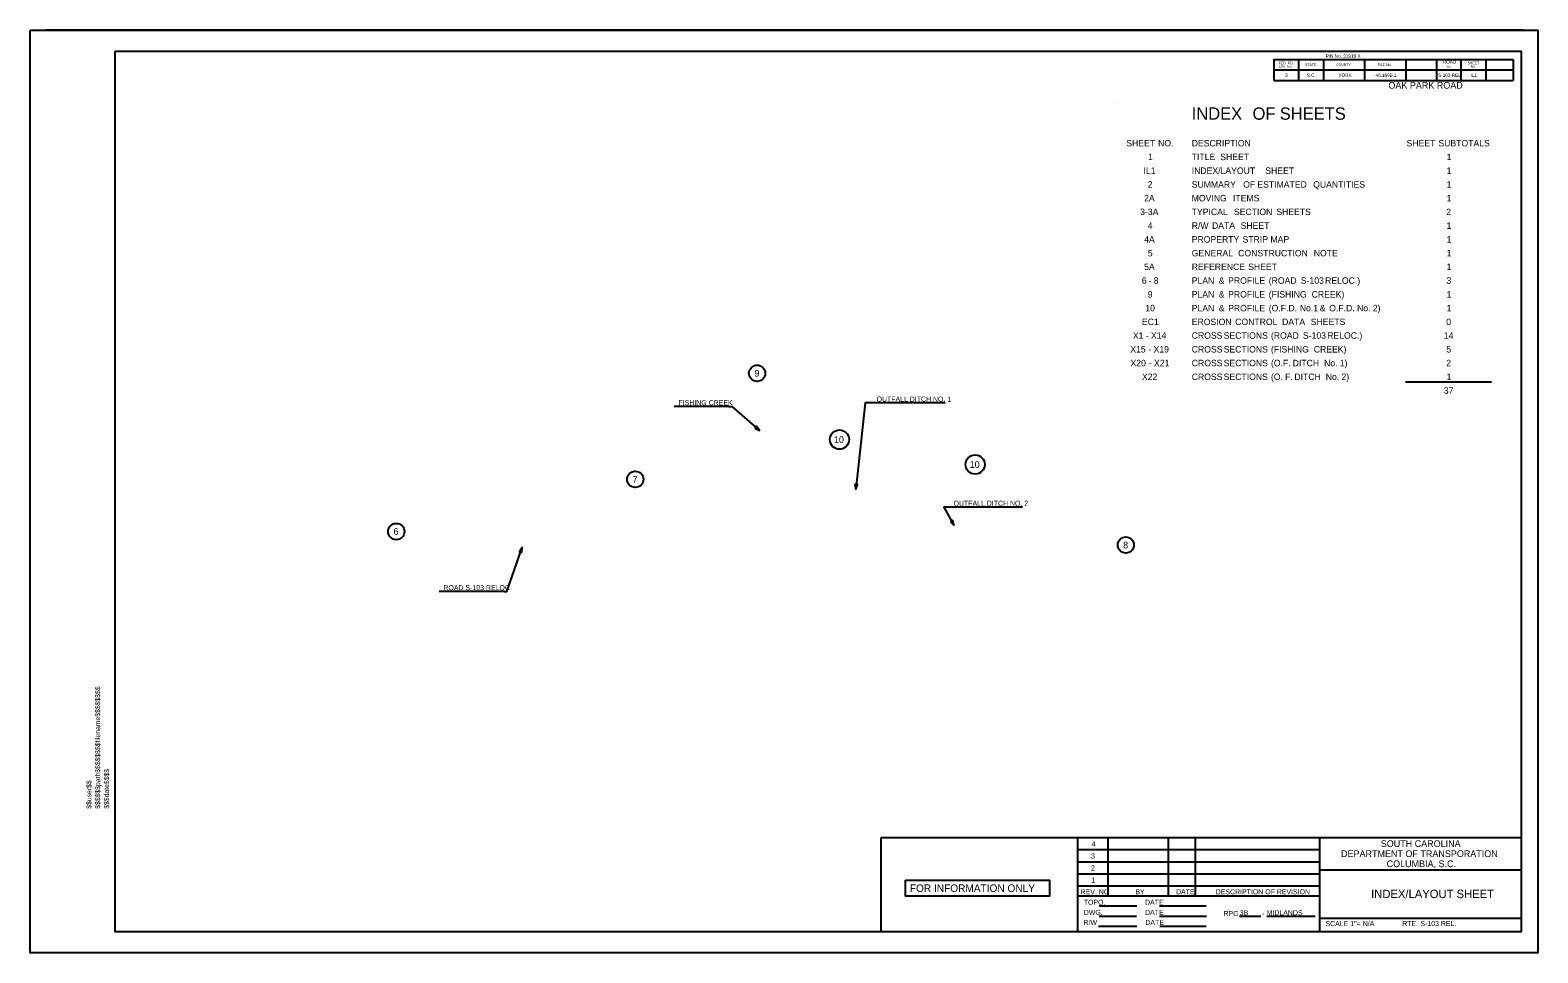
# Model space of a CAD drawing. Extents: x -796 to 2793, y -4650 to 4425.
# Drawn here: x 981 to 2777, y -125 to 975 of the extents above; entities that cross this region are included whole.
import ezdxf

# ---------------------------------------------------------------- set-up
doc = ezdxf.new("R2010")
doc.units = 0
for name, color, linetype in [('RD_HC_CL', 7, 'Continuous'), ('RD_HC_Data', 7, 'Continuous'), ('RD_HC_Data_Tic', 7, 'Continuous'), ('RD_SHT_Bndy', 7, 'Continuous'), ('RD_TX_Misc1', 7, 'Continuous')]:
    doc.layers.add(name, color=color, linetype=linetype)

msp = doc.modelspace()

# ---------------------------------------------------------------- linework, layer by layer
at = {"layer": 'RD_HC_CL'}
msp.add_lwpolyline([(981.4, 975), (2777.4, 975), (2777.4, -125), (981.4, -125)], close=True, dxfattribs=at)
at = {"layer": 'RD_HC_Data'}
for p, q in [((2760, 975), (1000, 975)), ((1000, 975), (2760, 975)), ((2463.1, 940), (2463.1, 915)), ((2463.1, 940), (2748.1, 940)), ((2492.1, 940), (2492.1, 915)), ((2522.1, 940), (2522.1, 915)), ((2571.1, 940), (2571.1, 915)), ((2620.1, 940), (2620.1, 915)), ((2656.6, 940), (2656.6, 915)), ((2685.6, 940), (2685.6, 915)), ((2715.6, 940), (2715.6, 915)), ((2748.1, 940), (2748.1, 915)), ((2463.1, 927.5), (2748.1, 927.5)), ((2463.1, 915), (2748.1, 915)), ((1995, 12.5), (2757.6, 12.5)), ((1995, -100), (1995, 12.5)), ((2229.6, -100), (2229.6, 12.5)), ((2229.6, 12.5), (2229.6, 12.5)), ((2265.6, -57.2), (2265.6, 12.5)), ((2337.6, -57.2), (2337.6, 12.5)), ((2369.4, -57.1), (2369.4, 12.5)), ((2517.6, -100), (2517.6, 12.5)), ((2229.6, -1.9), (2517.6, -1.9)), ((2229.6, -16.3), (2517.6, -16.3)), ((2229.6, -30.7), (2517.6, -30.7)), ((2517.6, -25.9), (2757.6, -25.9)), ((2229.6, -45.1), (2517.6, -45.1)), ((2229.6, -57.1), (2517.6, -57.1)), ((2255, -69.1), (2299.9, -69.1)), ((2326.8, -69.1), (2382.1, -69.1)), ((2255, -81.1), (2299.5, -81.1)), ((2326.8, -81.1), (2382.5, -81.1)), ((2422.1, -81.1), (2447.3, -81.1)), ((2454.5, -81.1), (2512, -81.1)), ((2517.6, -83.5), (2757.6, -83.5)), ((2254.2, -93.1), (2299.9, -93.1)), ((2327.2, -93.1), (2382.1, -93.1)), ((2760, -125), (1000, -125)), ((2760, -125), (1000, -125))]:
    msp.add_line(p, q, dxfattribs=at)
msp.add_lwpolyline([(1082.6, 950), (2757.6, 950), (2757.6, -100), (1082.6, -100)], close=True, dxfattribs=at)
at = {"layer": 'RD_HC_Data_Tic'}
msp.add_lwpolyline([(2024.3, -38.4), (2195.8, -38.4), (2195.8, -57.4), (2024.3, -57.4)], close=True, dxfattribs=at)
for centre, radius in [((1847.4, 565.9), 9.73), ((1945.5, 486.9), 11.5), ((2107.1, 457.2), 11.5), ((1702.2, 439.5), 9.72), ((1417.5, 377.3), 9.73), ((2286.6, 361.2), 9.67)]:
    msp.add_circle(centre, radius, dxfattribs=at)
at = {"layer": 'RD_SHT_Bndy'}
for p, q in [((2277.7, 887.3), (2277.7, 887.3)), ((2619.7, 555.6), (2722, 555.6)), ((1813.6, 526.4), (1748.7, 526.4)), ((2071.4, 530.7), (1984.7, 530.7)), ((2163.7, 406.5), (2076.4, 406.5)), ((1546.1, 305.9), (1468.7, 305.9))]:
    msp.add_line(p, q, dxfattribs=at)
for points in [[(1813.6, 526.4), (1817.1, 526.4), (1850.2, 497.8)], [(1984.7, 530.7), (1975.9, 530.7), (1964.9, 427.8)], [(2076.4, 406.5), (2069.8, 406.5), (2081.9, 384.7)], [(1546.1, 305.9), (1549.3, 305.9), (1567.6, 358.1)]]:
    msp.add_lwpolyline(points, dxfattribs=at)
for points in [[(1844.8, 500.4), (1850.2, 497.8), (1846.8, 502.7)], [(1963.9, 433.8), (1964.9, 427.8), (1967, 433.4)], [(2077.7, 389), (2081.9, 384.7), (2080.4, 390.5)], [(1567.2, 352.1), (1567.6, 358.1), (1564.2, 353.1)]]:
    msp.add_lwpolyline(points, close=True, dxfattribs=at)

# ---------------------------------------------------------------- texts
at = {"layer": 'RD_HC_Data_Tic'}
for s, height, p in [('FED. RD.', 3, (2468.7, 934.3)), ('STATE', 3, (2500.1, 932.3)), ('PIN No. 31919 X   ', 4, (2524.7, 942)), ('COUNTY', 3, (2537.1, 932.3)), ('FILE No.', 3, (2586.6, 932.3)), ('      ROAD      ', 4, (2655, 935.1)), ('SHEET', 3, (2693.7, 934.3)), ('DIV. No.', 3, (2469.3, 930.2)), ('3', 4, (2476.4, 919.3)), ('S.C.', 4, (2502.1, 919.3)), ('      YORK      ', 4, (2530.7, 919.3)), ('   46.169B.1    ', 4, (2579.4, 919.3)), ('   S-103 REL.   ', 4, (2653.9, 919.3)), ('No.', 3, (2667.9, 930.2)), ('      IL1       ', 4, (2688, 919.3)), ('No.', 3, (2697.4, 930.2)), ('OAK PARK ROAD                 ', 8, (2599.4, 905.2)), ('4', 6.24, (2245.8, 1.9)), ('SOUTH CAROLINA', 8, (2590.3, 1.2)), ('3', 6.24, (2245, -12.5)), ('DEPARTMENT OF TRANSPORATION', 8, (2543, -10.8)), ('COLUMBIA, S.C.', 8, (2597.3, -22.8)), ('2', 6.24, (2245, -26.9)), ('1', 6.24, (2245.4, -41.3)), ('FOR INFORMATION ONLY', 9, (2029.3, -52.4)), ('REV. NO.', 6, (2232.7, -55.2)), ('BY', 6, (2297.9, -55.2)), ('DATE', 6, (2346.4, -55.2)), ('DESCRIPTION OF REVISION', 6, (2393.7, -55.2)), ('      INDEX/LAYOUT SHEET       ', 10, (2556.5, -59.7)), ('TOPO.', 6, (2236.5, -67.7)), ('DATE', 6, (2309.5, -67.7)), ('R/W', 6, (2236.2, -91.7)), ('DWG.', 6, (2236.5, -79.7)), ('DATE', 6, (2309.5, -79.7)), ('DATE', 6, (2309.9, -91.7)), ('RPG', 6, (2403, -81.1)), ('3B    ', 6, (2422.3, -80.1)), ('-', 6, (2448.7, -81.1)), ('MIDLANDS   ', 6, (2454.3, -80.1)), ('SCALE 1"=', 6, (2524.4, -93.1)), ('N/A        ', 6, (2568.8, -93)), ('RTE.', 6, (2615.8, -93.1)), ('S-103 REL. ', 6, (2637.5, -93))]:
    msp.add_text(s, height=height, dxfattribs=at).set_placement(p)
at = {"layer": 'RD_SHT_Bndy'}
for s, height, p in [('INDEX', 14.7, (2365.1, 868.2)), (' OF', 14.7, (2432.1, 868.2)), (' SHEETS', 14.7, (2464.5, 868.2)), ('SHEET', 7.7, (2287.1, 836.4)), (' NO.', 7.7, (2322.2, 836.4)), ('DESCRIPTION', 7.7, (2365.1, 836.4)), ('SHEET', 7.7, (2621, 836.4)), (' SUBTOTALS', 7.7, (2656.1, 836.4)), ('1', 7.7, (2313.1, 820)), ('TITLE', 7.7, (2365.1, 820)), (' SHEET', 7.7, (2396.2, 820)), ('1', 7.7, (2668.7, 820)), ('IL1', 7.7, (2307.7, 803.6)), ('INDEX/LAYOUT', 7.7, (2365.1, 803.6)), (' SHEET', 7.7, (2449.8, 803.6)), ('1', 7.7, (2668.7, 803.6)), ('2', 7.7, (2312.7, 787.2)), ('SUMMARY', 7.7, (2365.1, 787.2)), (' OF', 7.7, (2423.5, 787.2)), (' ESTIMATED', 7.7, (2440.4, 787.2)), (' QUANTITIES', 7.7, (2506.9, 787.2)), ('1', 7.7, (2668.7, 787.2)), ('2A', 7.7, (2308.4, 770.9)), ('MOVING', 7.7, (2365.1, 770.9)), (' ITEMS', 7.7, (2411.4, 770.9)), ('1', 7.7, (2668.7, 770.9)), ('3-3A', 7.7, (2303.7, 754.5)), ('TYPICAL', 7.7, (2365.1, 754.5)), (' SECTION', 7.7, (2412.5, 754.5)), (' SHEETS', 7.7, (2463, 754.5)), ('2', 7.7, (2668.3, 754.5)), ('4', 7.7, (2312.7, 738.1)), ('R/W', 7.7, (2365.1, 738.1)), (' DATA', 7.7, (2386.4, 738.1)), (' SHEET', 7.7, (2420.5, 738.1)), ('1', 7.7, (2668.7, 738.1)), ('4A', 7.7, (2308.4, 721.7)), ('PROPERTY', 7.7, (2365.1, 721.7)), (' STRIP', 7.7, (2422.8, 721.7)), (' MAP', 7.7, (2456, 721.7)), ('1', 7.7, (2668.7, 721.7)), ('5', 7.7, (2312.8, 705.3)), ('GENERAL', 7.7, (2365.1, 705.3)), (' CONSTRUCTION', 7.7, (2417.6, 705.3)), (' NOTE', 7.7, (2507.6, 705.3)), ('1', 7.7, (2668.7, 705.3)), ('5A', 7.7, (2308.4, 689)), ('REFERENCE', 7.7, (2365.1, 689)), (' SHEET', 7.7, (2429.5, 689)), ('1', 7.7, (2668.7, 689)), ('6', 7.7, (2305.7, 672.6)), (' -', 7.7, (2310.9, 672.6)), (' 8', 7.7, (2317, 672.6)), ('PLAN', 7.7, (2365.1, 672.6)), (' &', 7.7, (2394.5, 672.6)), (' PROFILE', 7.7, (2405.6, 672.6)), (' (ROAD', 7.7, (2454, 672.6)), (' S-103', 7.7, (2492.2, 672.6)), (' RELOC.)', 7.7, (2521.1, 672.6)), ('3', 7.7, (2668.5, 672.6)), ('10', 7.7, (2309.8, 639.8)), ('9', 7.7, (2312.7, 656.2)), ('PLAN', 7.7, (2365.1, 656.2)), ('PLAN', 7.7, (2365.1, 639.8)), (' &', 7.7, (2394.5, 656.2)), (' &', 7.7, (2394.5, 639.8)), (' PROFILE', 7.7, (2405.6, 656.2)), (' PROFILE', 7.7, (2405.6, 639.8)), (' (FISHING', 7.7, (2454, 656.2)), (' (O.F.D.', 7.7, (2454, 639.8)), (' No.1', 7.7, (2491, 639.8)), (' CREEK)', 7.7, (2505.1, 656.2)), (' &', 7.7, (2514.8, 639.8)), (' O.F.D.', 7.7, (2526, 639.8)), (' No.', 7.7, (2559.2, 639.8)), (' 2)', 7.7, (2577.9, 639.8)), ('1', 7.7, (2668.7, 656.2)), ('1', 7.7, (2668.7, 639.8)), ('EC1', 7.7, (2305.8, 623.4)), ('EROSION', 7.7, (2365.1, 623.4)), (' CONTROL', 7.7, (2414, 623.4)), (' DATA', 7.7, (2469.9, 623.4)), (' SHEETS', 7.7, (2504, 623.4)), ('0', 7.7, (2668.3, 623.4)), ('X1', 7.7, (2295, 607.1)), (' X14', 7.7, (2313.7, 607.1)), ('CROSS', 7.7, (2365.1, 607.1)), (' SECTIONS', 7.7, (2400.3, 607.1)), (' (ROAD', 7.7, (2456.6, 607.1)), (' S-103', 7.7, (2494.7, 607.1)), (' RELOC.)', 7.7, (2523.6, 607.1)), ('14', 7.7, (2665.4, 607.1)), ('X15', 7.7, (2291.9, 590.7)), (' -', 7.7, (2307.6, 607.1)), (' -', 7.7, (2310.6, 590.7)), (' X19', 7.7, (2316.8, 590.7)), ('CROSS', 7.7, (2365.1, 590.7)), (' SECTIONS', 7.7, (2400.3, 590.7)), (' (FISHING', 7.7, (2456.6, 590.7)), (' CREEK)', 7.7, (2507.6, 590.7)), ('5', 7.7, (2668.4, 590.7)), ('X20', 7.7, (2292.2, 574.3)), (' -', 7.7, (2311.2, 574.3)), (' X21', 7.7, (2317.3, 574.3)), ('CROSS', 7.7, (2365.1, 574.3)), (' SECTIONS', 7.7, (2400.3, 574.3)), (' (O.F.', 7.7, (2456.6, 574.3)), (' DITCH', 7.7, (2482.5, 574.3)), (' No.', 7.7, (2519.9, 574.3)), (' 1)', 7.7, (2538.6, 574.3)), ('2', 7.7, (2668.3, 574.3)), ('9', 8, (1844.2, 561.9)), ('X22', 7.7, (2305.8, 557.9)), ('CROSS', 7.7, (2365.1, 557.9)), (' SECTIONS', 7.7, (2400.3, 557.9)), (' (O.', 7.7, (2456.6, 557.9)), (' F.', 7.7, (2473.4, 557.9)), (' DITCH', 7.7, (2484.5, 557.9)), (' No.', 7.7, (2521.9, 557.9)), (' 2)', 7.7, (2540.6, 557.9)), ('1', 7.7, (2668.7, 557.9)), ('37', 7.7, (2665.4, 541.5)), ('FISHING CREEK', 6, (1753.7, 527.9)), ('OUTFALL DITCH NO. 1', 6, (1989.7, 532.2)), ('10', 8, (1938.9, 482.9)), ('10', 8, (2100.6, 453.2)), ('7', 8, (1699, 435.5)), ('OUTFALL DITCH NO. 2', 6, (2081.4, 408)), ('6', 8, (1414.3, 373.3)), ('8', 8, (2283.4, 357.2)), ('ROAD S-103 RELOC.', 6, (1473.7, 307.4))]:
    msp.add_text(s, height=height, dxfattribs=at).set_placement(p)
at = {"layer": 'RD_TX_Misc1'}
for s, p in [('$$$$$$path$$$$$$$$filename$$$$$$$$', (1064.8, 46.8)), ('$$$date$$$$', (1075.3, 46.8)), ('$$user$$', (1054.3, 46.8))]:
    msp.add_text(s, height=5.88, rotation=90, dxfattribs=at).set_placement(p)

doc.saveas('drawing.dxf')
